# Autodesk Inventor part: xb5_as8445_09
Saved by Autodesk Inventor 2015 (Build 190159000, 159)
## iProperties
Created: 2018-04
Part Number: xb5_as8445_09
Checked By: TraceParts S.A.
Material: Generic
Catalog Web Link: www.traceparts.com
Document SubType Name: Modeling
Designer: TraceParts
Density: 1 g/cm^3
Appearance: Default
Company: TraceParts S.A.
Author: TraceParts
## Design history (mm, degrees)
feature "xb5_as8445_09.ipt"
body "Solid1"
